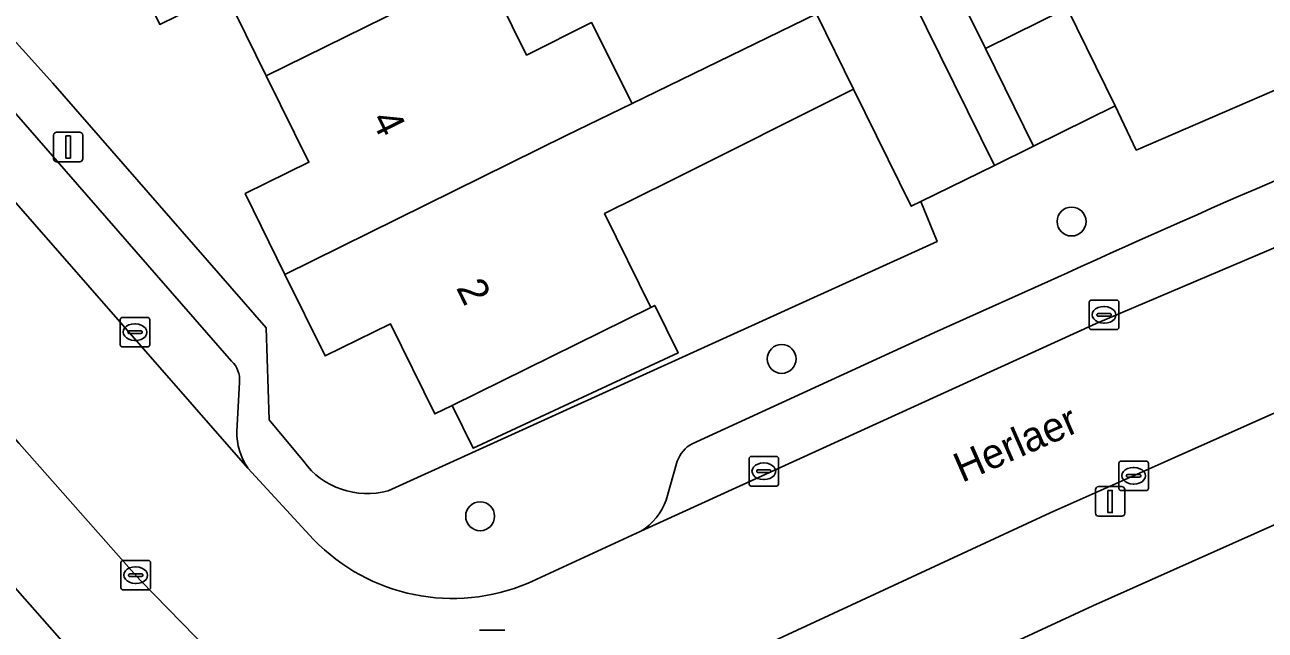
# Model space of a CAD drawing. Extents: x 157793 to 159380, y 380877 to 382313.
# Drawn here: x 158297.85 to 158339.85, y 381605.23 to 381625.72 of the extents above; entities that cross this region are included whole.
import ezdxf

# ---------------------------------------------------------------- set-up
doc = ezdxf.new("R2010")
doc.units = 0
for name, color, linetype in [('IMGEO_Boom', 7, 'Continuous'), ('IMGEO_Erf', 7, 'Continuous'), ('IMGEO_Kolk', 7, 'Continuous'), ('IMGEO_Lichtmast', 7, 'Continuous'), ('IMGEO_Openbare_ruimte_label', 7, 'Continuous'), ('IMGEO_Pand', 7, 'Continuous'), ('IMGEO_Pand_nummerreeks', 7, 'Continuous'), ('IMGEO_Parkeervlak_open', 7, 'Continuous'), ('IMGEO_Rijbaan_lokaal_open', 7, 'Continuous'), ('IMGEO_Rioolput', 7, 'Continuous'), ('IMGEO_Voetpad_open', 7, 'Continuous')]:
    doc.layers.add(name, color=color, linetype=linetype)

msp = doc.modelspace()

# ---------------------------------------------------------------- linework, layer by layer
at = {"layer": 'IMGEO_Boom'}
for centre in [(158333.296, 381619.062), (158323.48, 381614.412), (158313.27, 381609.089)]:
    msp.add_circle(centre, 0.489, dxfattribs=at)
at = {"layer": 'IMGEO_Erf'}
for points in [[(158357.891, 381632.022), (158357.474, 381634.854), (158357.349, 381634.82), (158356.929, 381637.479), (158357.035, 381637.497), (158355.528, 381647.674), (158355.39, 381647.644), (158355.08, 381650.055), (158355.182, 381650.084), (158354.779, 381653.233), (158354.383, 381656.383), (158353.993, 381659.534), (158353.778, 381661.419), (158353.626, 381662.753), (158336.89, 381655.945), (158317.871, 381649.781), (158297.433, 381638.997), (158286.293, 381632.925), (158289.537, 381630.734), (158292.834, 381630.367), (158298.799, 381623.74), (158306.027, 381615.459), (158306.126, 381612.351), (158307.296, 381610.939)], [(158327.318, 381631.063), (158330.379, 381624.916), (158333.143, 381626.278), (158334.773, 381622.971), (158335.487, 381621.481), (158343.075, 381624.761), (158350.508, 381627.629)], [(158313.397, 381627.62), (158314.841, 381624.694), (158317.046, 381625.794), (158318.413, 381623.055), (158324.657, 381626.095)], [(158306.03, 381623.987), (158304.632, 381626.823)], [(158310.153, 381609.954), (158328.741, 381618.381), (158328.197, 381619.737), (158327.87, 381619.576), (158325.917, 381623.539), (158319.717, 381620.443), (158317.486, 381619.33), (158319.051, 381616.154), (158319.184, 381616.22), (158319.974, 381614.617), (158313.035, 381611.392), (158312.323, 381612.837), (158311.739, 381612.549), (158310.233, 381615.604), (158308.022, 381614.514), (158306.661, 381617.274), (158305.315, 381620.005), (158307.47, 381621.067), (158306.03, 381623.987)], [(158304.839, 381598.226), (158304.646, 381598.587), (158290.211, 381614.948), (158288.497, 381616.726), (158288.122, 381616.541), (158287.742, 381616.353), (158287.57, 381616.702), (158287.95, 381616.889), (158288.214, 381617.02), (158283.808, 381622.001), (158283.116, 381622.732), (158282.361, 381623.399)], [(158355.743, 381615.281), (158353.591, 381614.531), (158346.202, 381611.49), (158334.016, 381606.06), (158319.848, 381599.488)]]:
    msp.add_lwpolyline(points, dxfattribs=at)
msp.add_arc((158309.441, 381612.526), 2.669, 216.4911, 285.4639, dxfattribs=at)
at = {"layer": 'IMGEO_Kolk'}
for p, q in [((158333.897, 381615.478), (158333.897, 381616.33)), ((158333.972, 381616.404), (158334.824, 381616.404)), ((158334.898, 381616.33), (158334.898, 381615.478)), ((158301.16, 381615.818), (158302.012, 381615.818)), ((158334.156, 381615.898), (158334.156, 381615.91)), ((158334.594, 381615.861), (158334.196, 381615.861)), ((158334.199, 381615.947), (158334.597, 381615.947)), ((158334.385, 381616.184), (158334.41, 381616.184)), ((158334.64, 381615.91), (158334.64, 381615.898)), ((158301.085, 381614.892), (158301.085, 381615.744)), ((158301.573, 381615.598), (158301.598, 381615.598)), ((158302.086, 381615.744), (158302.086, 381614.892)), ((158334.824, 381615.404), (158333.972, 381615.404)), ((158334.408, 381615.624), (158334.383, 381615.624)), ((158301.344, 381615.312), (158301.344, 381615.324)), ((158301.782, 381615.275), (158301.384, 381615.275)), ((158301.387, 381615.361), (158301.785, 381615.361)), ((158301.596, 381615.038), (158301.571, 381615.038)), ((158301.828, 381615.324), (158301.828, 381615.312)), ((158302.012, 381614.818), (158301.16, 381614.818)), ((158322.375, 381610.186), (158322.375, 381611.038)), ((158322.45, 381611.112), (158323.302, 381611.112)), ((158322.863, 381610.892), (158322.888, 381610.892)), ((158323.376, 381611.038), (158323.376, 381610.186)), ((158334.899, 381610.031), (158334.899, 381610.883)), ((158334.974, 381610.957), (158335.826, 381610.957)), ((158335.9, 381610.883), (158335.9, 381610.031)), ((158322.634, 381610.606), (158322.634, 381610.618)), ((158323.072, 381610.569), (158322.674, 381610.569)), ((158322.677, 381610.655), (158323.075, 381610.655)), ((158323.118, 381610.618), (158323.118, 381610.606)), ((158335.158, 381610.451), (158335.158, 381610.463)), ((158335.596, 381610.414), (158335.198, 381610.414)), ((158335.201, 381610.5), (158335.599, 381610.5)), ((158335.387, 381610.737), (158335.412, 381610.737)), ((158335.642, 381610.463), (158335.642, 381610.451)), ((158323.302, 381610.112), (158322.45, 381610.112)), ((158322.886, 381610.332), (158322.861, 381610.332)), ((158335.826, 381609.957), (158334.974, 381609.957)), ((158335.41, 381610.177), (158335.385, 381610.177)), ((158301.108, 381606.669), (158301.108, 381607.521)), ((158301.183, 381607.595), (158302.035, 381607.595)), ((158302.109, 381607.521), (158302.109, 381606.669)), ((158301.367, 381607.089), (158301.367, 381607.101)), ((158301.805, 381607.052), (158301.407, 381607.052)), ((158301.41, 381607.138), (158301.808, 381607.138)), ((158301.596, 381607.375), (158301.621, 381607.375)), ((158301.851, 381607.101), (158301.851, 381607.089)), ((158302.035, 381606.595), (158301.183, 381606.595)), ((158301.619, 381606.815), (158301.594, 381606.815))]:
    msp.add_line(p, q, dxfattribs=at)
for points in [[(158333.897, 381615.478), (158333.897, 381616.33)], [(158333.972, 381616.404), (158334.824, 381616.404)], [(158334.898, 381616.33), (158334.898, 381615.478)], [(158301.16, 381615.818), (158302.012, 381615.818)], [(158301.085, 381614.892), (158301.085, 381615.744)], [(158302.086, 381615.744), (158302.086, 381614.892)], [(158334.824, 381615.404), (158333.972, 381615.404)], [(158302.012, 381614.818), (158301.16, 381614.818)], [(158322.375, 381610.186), (158322.375, 381611.038)], [(158322.45, 381611.112), (158323.302, 381611.112)], [(158323.376, 381611.038), (158323.376, 381610.186)], [(158334.899, 381610.031), (158334.899, 381610.883)], [(158334.974, 381610.957), (158335.826, 381610.957)], [(158335.9, 381610.883), (158335.9, 381610.031)], [(158323.302, 381610.112), (158322.45, 381610.112)], [(158335.826, 381609.957), (158334.974, 381609.957)], [(158301.108, 381606.669), (158301.108, 381607.521)], [(158301.183, 381607.595), (158302.035, 381607.595)], [(158302.109, 381607.521), (158302.109, 381606.669)], [(158302.035, 381606.595), (158301.183, 381606.595)]]:
    msp.add_lwpolyline(points, dxfattribs=at)
for centre, radius, start, end in [((158333.974, 381616.328), 0.0765, 91.552, 178.448), ((158333.974, 381616.328), 0.0765, 91.552, 178.448), ((158334.822, 381616.328), 0.0765, 1.552, 88.448), ((158334.822, 381616.328), 0.0765, 1.552, 88.448), ((158301.162, 381615.742), 0.0765, 91.552, 178.448), ((158301.162, 381615.742), 0.0765, 91.552, 178.448), ((158302.01, 381615.742), 0.0765, 1.552, 88.448), ((158302.01, 381615.742), 0.0765, 1.552, 88.448), ((158334.196, 381615.907), 0.0403, 85.8775, 175.7526), ((158334.193, 381615.897), 0.0366, 178.938, 274.7102), ((158334.597, 381615.904), 0.043, 264.8664, 352.4533), ((158334.601, 381615.909), 0.0386, 1.7309, 96.639), ((158333.974, 381615.48), 0.0765, 181.552, 268.448), ((158333.974, 381615.48), 0.0765, 181.552, 268.448), ((158334.822, 381615.48), 0.0765, 271.552, 358.448), ((158334.822, 381615.48), 0.0765, 271.552, 358.448), ((158301.384, 381615.321), 0.0403, 85.8775, 175.7526), ((158301.381, 381615.311), 0.0366, 178.938, 274.7102), ((158301.785, 381615.318), 0.043, 264.8664, 352.4533), ((158301.789, 381615.323), 0.0386, 1.7309, 96.639), ((158301.162, 381614.894), 0.0765, 181.552, 268.448), ((158301.162, 381614.894), 0.0765, 181.552, 268.448), ((158302.01, 381614.894), 0.0765, 271.552, 358.448), ((158302.01, 381614.894), 0.0765, 271.552, 358.448), ((158322.452, 381611.036), 0.0765, 91.552, 178.448), ((158322.452, 381611.036), 0.0765, 91.552, 178.448), ((158323.3, 381611.036), 0.0765, 1.552, 88.448), ((158323.3, 381611.036), 0.0765, 1.552, 88.448), ((158334.976, 381610.881), 0.0765, 91.552, 178.448), ((158334.976, 381610.881), 0.0765, 91.552, 178.448), ((158335.824, 381610.881), 0.0765, 1.552, 88.448), ((158335.824, 381610.881), 0.0765, 1.552, 88.448), ((158322.674, 381610.615), 0.0403, 85.8775, 175.7526), ((158322.671, 381610.605), 0.0366, 178.938, 274.7102), ((158323.075, 381610.612), 0.043, 264.8664, 352.4533), ((158323.079, 381610.617), 0.0386, 1.7309, 96.639), ((158335.198, 381610.46), 0.0403, 85.8775, 175.7526), ((158335.195, 381610.45), 0.0366, 178.938, 274.7102), ((158335.599, 381610.457), 0.043, 264.8664, 352.4533), ((158335.603, 381610.462), 0.0386, 1.7309, 96.639), ((158322.452, 381610.188), 0.0765, 181.552, 268.448), ((158322.452, 381610.188), 0.0765, 181.552, 268.448), ((158323.3, 381610.188), 0.0765, 271.552, 358.448), ((158323.3, 381610.188), 0.0765, 271.552, 358.448), ((158334.976, 381610.033), 0.0765, 181.552, 268.448), ((158334.976, 381610.033), 0.0765, 181.552, 268.448), ((158335.824, 381610.033), 0.0765, 271.552, 358.448), ((158335.824, 381610.033), 0.0765, 271.552, 358.448), ((158301.185, 381607.519), 0.0765, 91.552, 178.448), ((158301.185, 381607.519), 0.0765, 91.552, 178.448), ((158302.033, 381607.519), 0.0765, 1.552, 88.448), ((158302.033, 381607.519), 0.0765, 1.552, 88.448), ((158301.407, 381607.098), 0.0403, 85.8775, 175.7526), ((158301.404, 381607.088), 0.0366, 178.938, 274.7102), ((158301.808, 381607.095), 0.043, 264.8664, 352.4533), ((158301.812, 381607.1), 0.0386, 1.7309, 96.639), ((158301.185, 381606.671), 0.0765, 181.552, 268.448), ((158301.185, 381606.671), 0.0765, 181.552, 268.448), ((158302.033, 381606.671), 0.0765, 271.552, 358.448), ((158302.033, 381606.671), 0.0765, 271.552, 358.448)]:
    msp.add_arc(centre, radius, start, end, dxfattribs=at)
for centre, major_axis, ratio, start_param, end_param in [((158334.384, 381615.904), (-0.387, 0.002), 0.722429, 4.712389, 7.853982), ((158334.409, 381615.904), (-0.39, 0.002), 0.717154, 1.570796, 4.712389), ((158301.572, 381615.318), (-0.387, 0.002), 0.722429, 4.712389, 7.853982), ((158301.597, 381615.318), (-0.39, 0.002), 0.717154, 1.570796, 4.712389), ((158322.862, 381610.612), (-0.387, 0.002), 0.722429, 4.712389, 7.853982), ((158322.887, 381610.612), (-0.39, 0.002), 0.717154, 1.570796, 4.712389), ((158335.386, 381610.457), (-0.387, 0.002), 0.722429, 4.712389, 7.853982), ((158335.411, 381610.457), (-0.39, 0.002), 0.717154, 1.570796, 4.712389), ((158301.595, 381607.095), (-0.387, 0.002), 0.722429, 4.712389, 7.853982), ((158301.62, 381607.095), (-0.39, 0.002), 0.717154, 1.570796, 4.712389)]:
    msp.add_ellipse(centre, major_axis=major_axis, ratio=ratio, start_param=start_param, end_param=end_param, dxfattribs=at)
at = {"layer": 'IMGEO_Lichtmast'}
for p, q in [((158298.826, 381621.185), (158298.826, 381621.985)), ((158298.826, 381621.985), (158298.826, 381621.185)), ((158298.926, 381622.085), (158299.716, 381622.085)), ((158299.716, 381622.085), (158298.926, 381622.085)), ((158299.816, 381621.985), (158299.816, 381621.185)), ((158299.816, 381621.185), (158299.816, 381621.985)), ((158299.716, 381621.085), (158298.926, 381621.085)), ((158298.926, 381621.085), (158299.716, 381621.085)), ((158334.106, 381609.19), (158334.106, 381609.99)), ((158334.106, 381609.99), (158334.106, 381609.19)), ((158334.206, 381610.09), (158334.996, 381610.09)), ((158334.996, 381610.09), (158334.206, 381610.09)), ((158335.096, 381609.99), (158335.096, 381609.19)), ((158335.096, 381609.19), (158335.096, 381609.99)), ((158334.996, 381609.09), (158334.206, 381609.09)), ((158334.206, 381609.09), (158334.996, 381609.09))]:
    msp.add_line(p, q, dxfattribs=at)
for points in [[(158299.246, 381621.96), (158299.396, 381621.96), (158299.396, 381621.21), (158299.246, 381621.21), (158299.246, 381621.96)], [(158334.526, 381609.965), (158334.676, 381609.965), (158334.676, 381609.215), (158334.526, 381609.215), (158334.526, 381609.965)]]:
    msp.add_lwpolyline(points, dxfattribs=at)
for centre, start, end in [((158298.926, 381621.985), 90, 180), ((158298.926, 381621.985), 90, 180), ((158299.716, 381621.985), 0, 90), ((158299.716, 381621.985), 360, 90), ((158298.926, 381621.185), 180, 270), ((158298.926, 381621.185), 180, 270), ((158299.716, 381621.185), 270, 0), ((158299.716, 381621.185), 270, 0), ((158334.206, 381609.99), 90, 180), ((158334.206, 381609.99), 90, 180), ((158334.996, 381609.99), 0, 90), ((158334.996, 381609.99), 360, 90), ((158334.206, 381609.19), 180, 270), ((158334.206, 381609.19), 180, 270), ((158334.996, 381609.19), 270, 0), ((158334.996, 381609.19), 270, 0)]:
    msp.add_arc(centre, 0.1, start, end, dxfattribs=at)
at = {"layer": 'IMGEO_Pand'}
for points in [[(158306.03, 381623.987), (158313.397, 381627.62), (158311.912, 381630.636), (158310.596, 381633.17), (158301.031, 381628.547), (158302.419, 381625.732), (158304.632, 381626.823)], [(158318.413, 381623.055), (158317.046, 381625.794), (158314.841, 381624.694), (158313.397, 381627.62), (158306.03, 381623.987), (158307.47, 381621.067), (158305.315, 381620.005), (158306.661, 381617.274), (158316.183, 381621.969)], [(158327.469, 381627.481), (158324.657, 381626.095), (158325.917, 381623.539), (158327.87, 381619.576), (158328.197, 381619.737), (158330.682, 381620.962)], [(158317.486, 381619.33), (158319.717, 381620.443), (158325.917, 381623.539), (158324.657, 381626.095), (158318.413, 381623.055), (158316.183, 381621.969), (158306.661, 381617.274), (158308.022, 381614.514), (158310.233, 381615.604), (158311.739, 381612.549), (158312.323, 381612.837), (158319.051, 381616.154)], [(158332.01, 381621.608), (158334.773, 381622.971), (158333.143, 381626.278), (158330.379, 381624.916)], [(158319.974, 381614.617), (158319.184, 381616.22), (158319.051, 381616.154), (158312.323, 381612.837), (158313.035, 381611.392)]]:
    msp.add_lwpolyline(points, close=True, dxfattribs=at)
at = {"layer": 'IMGEO_Parkeervlak_open'}
for points in [[(158289.912, 381628.021), (158294.557, 381623.1), (158305.402, 381610.721)], [(158304.856, 381614.338), (158302.314, 381617.249), (158298.945, 381621.109), (158293.654, 381627.168)], [(158318.715, 381608.58), (158334.134, 381615.613), (158352.571, 381623.44)], [(158333.154, 381617.326), (158328.628, 381615.291), (158320.452, 381611.542)], [(158305.028, 381611.958), (158305.123, 381613.629)], [(158319.946, 381610.952), (158319.574, 381609.632)]]:
    msp.add_lwpolyline(points, dxfattribs=at)
for centre, radius, start, end in [((158502.245, 381245.651), 408.331, 112.06193, 114.46277), ((158304.25, 381613.705), 0.876, 355.0294, 46.242), ((158307.223, 381611.947), 2.195, 179.7009, 213.9439), ((158320.933, 381610.617), 1.042, 117.4895, 161.2759), ((158317.603, 381610.365), 2.103, 301.9241, 339.6099)]:
    msp.add_arc(centre, radius, start, end, dxfattribs=at)
at = {"layer": 'IMGEO_Rijbaan_lokaal_open'}
for points in [[(158307.632, 381608.303), (158305.402, 381610.721), (158294.557, 381623.1), (158289.912, 381628.021), (158289.436, 381628.504), (158285.728, 381624.845), (158286.794, 381623.735), (158289.868, 381620.297), (158291.098, 381618.921), (158294.153, 381615.504), (158294.454, 381615.166), (158297.663, 381611.546), (158298.877, 381610.178), (158301.455, 381607.269), (158301.773, 381606.911), (158304.092, 381604.53), (158305.281, 381603.486), (158306.107, 381602.96), (158308.774, 381601.478), (158310.468, 381600.286), (158317.867, 381602.39), (158325.082, 381605.727)], [(158325.082, 381605.727), (158332.577, 381609.207), (158336.433, 381610.914), (158344.86, 381614.672), (158354.482, 381618.62), (158352.571, 381623.44), (158334.134, 381615.613), (158318.715, 381608.58), (158314.894, 381606.825)]]:
    msp.add_lwpolyline(points, dxfattribs=at)
msp.add_arc((158312.338, 381612.844), 6.539, 223.9779, 293.014, dxfattribs=at)
at = {"layer": 'IMGEO_Rioolput'}
msp.add_line((158313.254, 381605.233), (158314.106, 381605.233), dxfattribs=at)
msp.add_lwpolyline([(158313.254, 381605.233), (158314.106, 381605.233)], dxfattribs=at)
at = {"layer": 'IMGEO_Voetpad_open'}
msp.add_lwpolyline([(158327.318, 381631.063), (158325.952, 381633.836), (158324.585, 381636.609), (158322.534, 381640.77), (158322.478, 381640.743), (158321.259, 381640.142), (158323.317, 381635.968), (158324.688, 381633.188), (158326.059, 381630.408), (158327.469, 381627.481), (158330.682, 381620.962), (158332.01, 381621.608), (158330.379, 381624.916)], close=True, dxfattribs=at)
for points in [[(158307.296, 381610.939), (158306.126, 381612.351), (158306.027, 381615.459), (158298.799, 381623.74), (158292.834, 381630.367), (158289.537, 381630.734), (158286.293, 381632.925), (158284.609, 381633.795)], [(158356.907, 381630.003), (158350.508, 381627.629), (158343.075, 381624.761), (158335.487, 381621.481), (158334.773, 381622.971), (158332.01, 381621.608), (158330.682, 381620.962), (158328.197, 381619.737), (158328.741, 381618.381), (158310.153, 381609.954)], [(158293.654, 381627.168), (158298.945, 381621.109), (158302.314, 381617.249), (158304.856, 381614.338)], [(158277.038, 381625.757), (158277.874, 381625.593), (158278.843, 381625.319), (158279.783, 381624.959), (158280.688, 381624.517), (158281.549, 381623.995), (158282.361, 381623.399), (158283.116, 381622.732), (158283.808, 381622.001), (158288.214, 381617.02), (158288.52, 381617.171), (158288.692, 381616.822), (158288.497, 381616.726), (158290.211, 381614.948), (158304.646, 381598.587), (158310.003, 381593.502), (158311.884, 381591.846), (158313.944, 381592.625), (158312.131, 381597.246), (158311.373, 381599.121)], [(158310.468, 381600.286), (158308.774, 381601.478), (158306.107, 381602.96), (158305.281, 381603.486), (158304.092, 381604.53), (158301.773, 381606.911), (158301.455, 381607.269), (158298.877, 381610.178), (158297.663, 381611.546), (158294.454, 381615.166), (158294.153, 381615.504), (158291.098, 381618.921), (158289.868, 381620.297), (158286.794, 381623.735)], [(158355.432, 381618.94), (158354.482, 381618.62), (158344.86, 381614.672), (158336.433, 381610.914), (158332.577, 381609.207), (158325.082, 381605.727), (158317.867, 381602.39)], [(158320.452, 381611.542), (158328.628, 381615.291), (158333.154, 381617.326)], [(158305.123, 381613.629), (158305.028, 381611.958)], [(158319.848, 381599.488), (158334.016, 381606.06), (158346.202, 381611.49)], [(158319.574, 381609.632), (158319.946, 381610.952)], [(158305.402, 381610.721), (158307.632, 381608.303)], [(158314.894, 381606.825), (158318.715, 381608.58)]]:
    msp.add_lwpolyline(points, dxfattribs=at)
for centre, radius, start, end in [((158502.245, 381245.651), 408.331, 112.06193, 114.46277), ((158304.25, 381613.705), 0.876, 355.0294, 46.242), ((158307.223, 381611.947), 2.195, 179.7009, 213.9439), ((158320.933, 381610.617), 1.042, 117.4895, 161.2759), ((158309.441, 381612.526), 2.669, 216.4911, 285.4639), ((158317.603, 381610.365), 2.103, 301.9241, 339.6099), ((158312.338, 381612.844), 6.539, 223.9779, 293.014)]:
    msp.add_arc(centre, radius, start, end, dxfattribs=at)

# ---------------------------------------------------------------- texts
at = {"layer": 'IMGEO_Openbare_ruimte_label'}
msp.add_text('Herlaer', height=1, rotation=23.6425, dxfattribs=at).set_placement((158329.589, 381610.216))
at = {"layer": 'IMGEO_Pand_nummerreeks'}
for s, rotation, p in [('4', 296.2456, (158309.562, 381622.524)), ('2', 296.2413, (158312.443, 381616.82))]:
    msp.add_text(s, height=1, rotation=rotation, dxfattribs=at).set_placement(p)

doc.saveas('drawing.dxf')
